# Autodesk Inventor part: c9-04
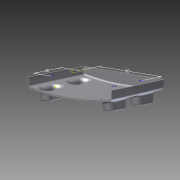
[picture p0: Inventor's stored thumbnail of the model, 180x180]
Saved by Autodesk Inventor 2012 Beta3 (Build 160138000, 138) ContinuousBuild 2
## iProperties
Created: 2010-12
Part Number: c9-04
Material: Default
Document SubType Name: Modeling
Designer: Beta-8540w
Density: 1 g/cm^3
Author: Beta-8540w
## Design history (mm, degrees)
sketch "Sketch1"
  geometry: L1 (-60, -12)-(60, -12); L2 (60, -12)-(60, 12); L3 (60, 12)-(-60, 12); L4 (-60, 12)-(-60, -12); A1 r 350 centre (0, -332.819) between (60, 12) and (-60, 12); A2 r 350 centre (0, 332.819) between (-60, -12) and (60, -12); 3 further points
  constraints: 8 end point, 4 point on circle, 2 centre point, 2 midpoint, 2 parallel, 1 equal radius, 1 horizontal, 1 horizontal alignment, 1 perpendicular, 1 vertical alignment
  dimensions: "d0" = 120 distance of L3.end L2.end; "d1" = 24 distance of L2.end L1.end; "d2" = 350 radius of A1
workplane "Work Plane4"
sketch "Sketch5"
  geometry: L1 (-60, 12)-(-60, -12) reference; L2 (60, -12)-(60, 12) reference; L3 (-58, 10.314)-(-58, -10.314); L4 (58, -10.314)-(58, 10.314); A1 r 350 centre (0, 332.819) between (-60, -12) and (60, -12) reference; A2 r 350 centre (0, -332.819) between (60, 12) and (-60, 12) reference; A3 r 348 centre (0, 332.819) between (-58, -10.314) and (58, -10.314); A4 r 348 centre (0, -332.819) between (58, 10.314) and (-58, 10.314); 1 further point
  constraints: 4 end point, 4 point on circle, 2 centre point, 3 other
  dimensions: "d37" = 2 distance between parallel lines of L2 L4
sketch "Sketch6"
  geometry: L1 (-60, 0)-(60, 0); L2 (60, 0)-(58.843, 22.085); L3 (-60, 0)-(-58.779, 23.307); A1 r 691.758 centre (630.81, -36.204) between (-60, 0) and (-58, -100); A2 r 691.758 centre (-630.81, -36.204) between (58, -100) and (60, 0); 1 further point
  constraints: 6 end point, 4 point on circle, 2 centre point, 2 tangent, 1 horizontal
  dimensions: "d53" = 87 deg angle of L1 L3; "d54" = 87 deg angle of L1 L2 (= d53)
sketch "Sketch7"
  geometry: L1 (17.181, 0)-(12, 0) reference; L2 (15.181, -100)-(10.314, -100) reference; L3 (17.181, 0)-(16.768, 11.838); A1 r 911.322 centre (-893.585, -31.805) between (15.181, -100) and (17.181, 0); 1 further point
  constraints: 2 end point, 2 point on circle, 1 centre point, 1 tangent
  dimensions: "d56" = 88 deg angle of L1 L3
feature "LoftSrf2" sketch "Sketch5", "Sketch6", "Sketch7" dims "d57" = 0, "d58" = 90 deg, "d59" = 0, "d60" = 90 deg, "d61" = 0, "d62" = 90 deg, "d63" = 0, "d64" = 90 deg, "d65" = 0, "d66" = 90 deg
sketch "Sketch2"
  geometry: L1 (-75, -16)-(75, -16); L2 (-75, -60)-(75, -60); A1 r 183.781 centre (0, -183.781) between (75, -16) and (-75, -16); 2 further points
  constraints: 4 end point, 3 point on circle, 1 centre point, 1 coincident, 1 horizontal, 1 parallel
  dimensions: "d5" = 16 distance from line of point (0, 0) L1; "d7" = 60 distance from line of point (0, 0) L2; "d55" = 150 distance of L1.start L1.end
feature "RevolutionSrf1" sketch "Sketch2" dims angle "d8" = 40 deg
patch "Boundary Patch1" dims "d13" = 0, "d67" = 0, "d68" = 0, "d69" = 0, "d70" = 0
workplane "Work Plane1"
sketch "Sketch3"
  geometry: L1 (52, -85)-(52, -73); L2 (38, -73)-(38, -85); A1 r 7 centre (45, -73) between (52, -73) and (38, -73); A2 r 7 centre (45, -85) between (38, -85) and (52, -85); 1 further point
  constraints: 4 end point, 4 point on circle, 4 tangent, 2 centre point, 1 parallel, 1 vertical
  dimensions: "d15" = 12 distance of L1.start L1.end; "d16" = 7 radius of A1; "d50" = 45 horizontal distance of A1.centre point (0, 0); "d51" = 85 vertical distance of point (0, 0) A2.centre
extrude_surface "ExtrusionSrf2" sketch "Sketch3" dims "d19" = 14, "d20" = 5 deg
pattern_linear "Rectangular Pattern1" dims "d23" = 90
workplane "Work Plane2"
feature "Sculpt1"
sketch "Sketch4"
  geometry: L1 (-24.5, 6)-(24.5, 6); L2 (27.5, 3)-(27.5, -3); L3 (24.5, -6)-(-24.5, -6); L4 (-27.5, -3)-(-27.5, 3); A1 r 3 centre (-24.5, 3) between (-24.5, 6) and (-27.5, 3); A2 r 3 centre (24.5, 3) between (27.5, 3) and (24.5, 6); A3 r 3 centre (24.5, -3) between (24.5, -6) and (27.5, -3); A4 r 3 centre (-24.5, -3) between (-27.5, -3) and (-24.5, -6); 6 further points
  constraints: 8 end point, 8 point on circle, 8 tangent, 6 point on line, 4 centre point, 3 equal radius, 2 midpoint, 2 parallel, 1 horizontal, 1 horizontal alignment, 1 perpendicular, 1 vertical alignment
  dimensions: "d28" = 55 distance of point (27.5, -6) point (-27.5, -6); "d29" = 12 distance of point (27.5, 6) point (27.5, -6); "d30" = 3 radius of A1
extrude_surface "ExtrusionSrf6" sketch "Sketch4" dims "d31" = 14, "d32" = 45 deg
patch "Boundary Patch2" dims "d33" = 0, "d34" = 0
fillet "Fillet1" dims "d79" = 4, "d80" = 3, "d81" = 1
feature "Sculpt2"
node "Splitting Plane 1"
shell "Shell1" dims "d83" = 2
split "Split1"
  body "Solid1"
feature "Lip1" dims "d92" = 1, "d93" = 1, "d94" = 0, "d95" = 0, "d96" = 0, "d97" = 0
feature "Lip2" dims "d98" = 1, "d99" = 1, "d100" = 0, "d101" = 0, "d102" = 0, "d103" = 0.5
split "Split3"
  node "Back"
sketch "Sketch9"
  geometry: L1 (50.167, -73)-(50.167, -85) reference; L2 (39.833, -85)-(39.833, -73) reference; L3 (45, -73)-(45, -85); L4 (45, -85)-(39.833, -85); A1 r 5.167 centre (45, -73) between (50.167, -73) and (39.833, -73) reference; A2 r 5.167 centre (45, -85) between (39.833, -85) and (50.167, -85) reference; 5 further points
  constraints: 4 end point, 1 horizontal, 1 midpoint, 1 parallel, 1 perpendicular, 1 vertical, 3 other
  dimensions: "d86" = 90 distance of point (45, -79) point (-45, -79); "d89" = 40 distance of point (45, -79) point (45, -39)
  node "Projected Loop1"
body "Srf2"
body "Srf3"
body "Srf4"
body "Srf5"
body "Srf6"
body "Srf7"
body "Srf8"
body "Srf9"
body "Srf11"
feature "Stitch Surface1"
body "Srf12"
extrude_surface "ExtrusionSrf3"
extrude_surface "ExtrusionSrf4"
extrude_surface "ExtrusionSrf5"
node "Front"
node "Back - Top"
node "Back - Bottom"
other parameters: "d14" = -24, "d52" = -6
